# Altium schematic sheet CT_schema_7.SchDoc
size 242 x 245 mm
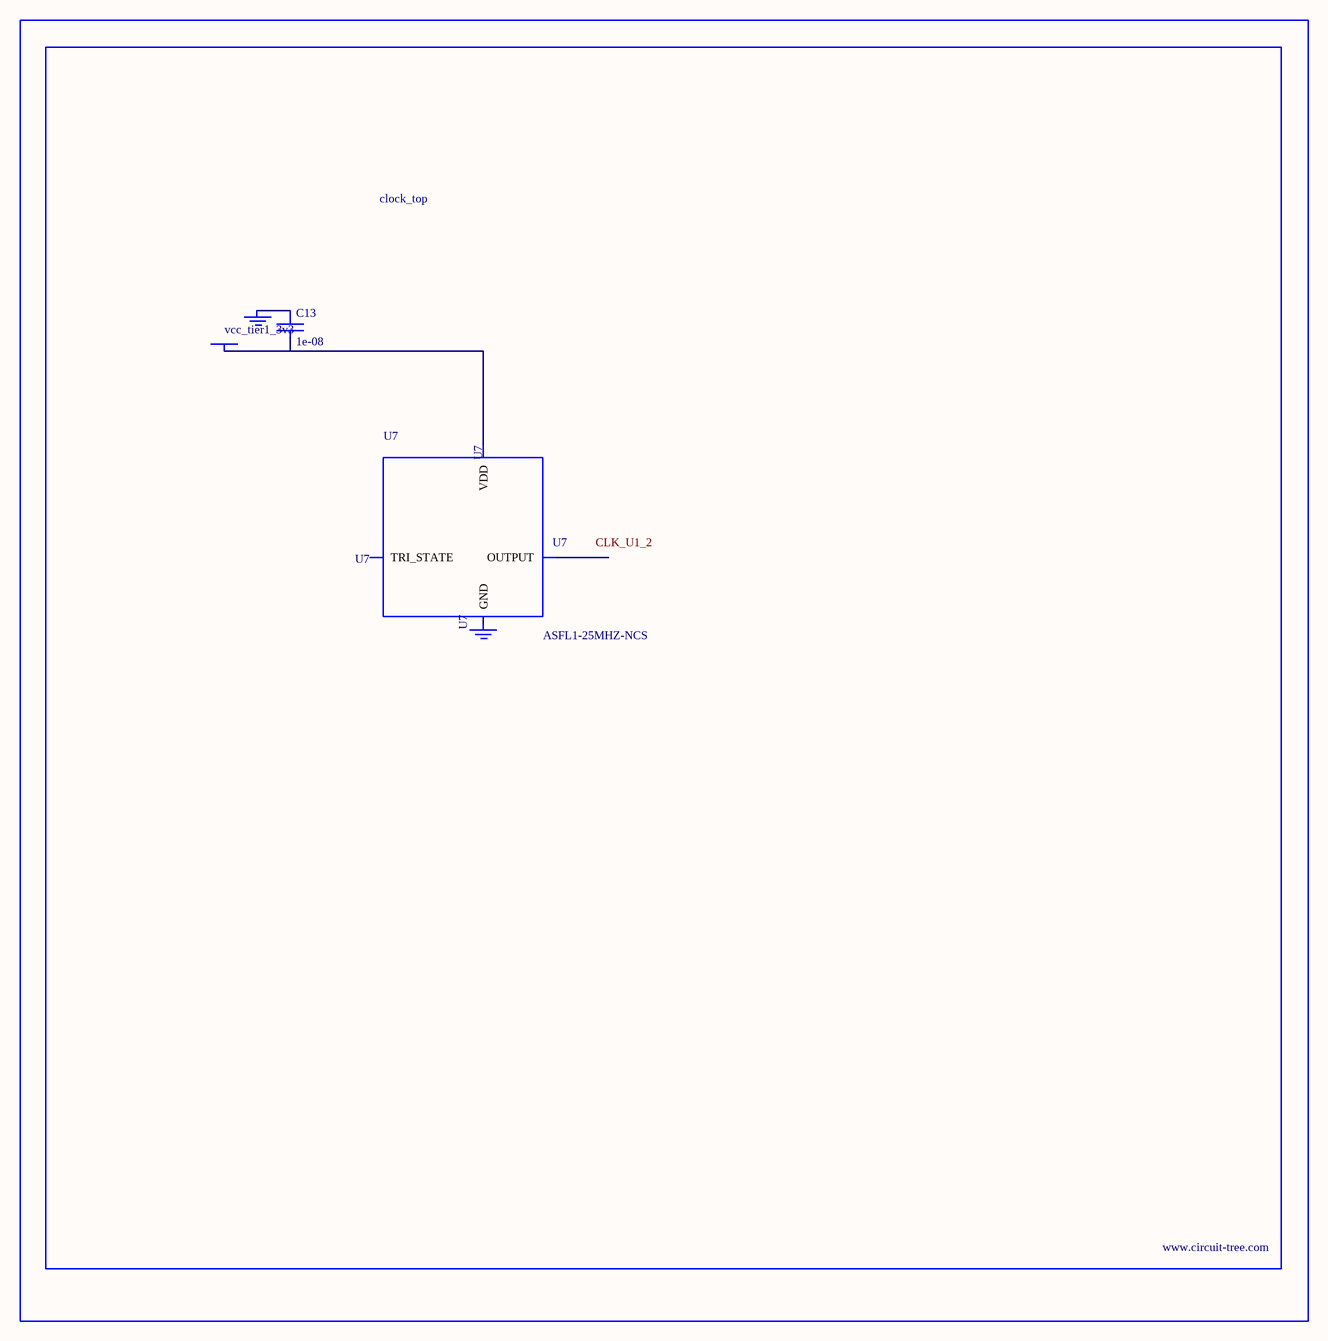
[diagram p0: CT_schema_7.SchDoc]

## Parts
BORDER6  (no value)
C13  1e-08  [C0402]
GND_INSTANCE_6_0  (no value)
GND_INSTANCE_6_1  (no value)
POWER_INSTANCE_6_0  vcc_tier1_3v3
U7  ASFL1-25MHZ-NCS  [ASFL1]

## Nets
NetC13_1: C13.1 GND_INSTANCE_6_0.0(GND)
NetC13_2: C13.2 POWER_INSTANCE_6_0.0(PWR) U7.4(VDD)

Not connected (* = marked no-connect by the designer): GND_INSTANCE_6_1 0(GND); U7 1(TRI_STATE) 2(GND) 3(OUTPUT)

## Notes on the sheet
- Labels drawn without touching a wire or pin: CLK_U1_2

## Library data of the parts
BORDER6 = BORDER_PAGE6
C13 = C0402C103K3RAC
GND_INSTANCE_6_0 GND_INSTANCE_6_1 = GND
POWER_INSTANCE_6_0 = PWR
